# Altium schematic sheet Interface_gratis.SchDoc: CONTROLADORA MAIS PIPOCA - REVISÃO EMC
size A3; DocumentNumber: GA0050; SheetNumber: 17; SheetTotal: 17
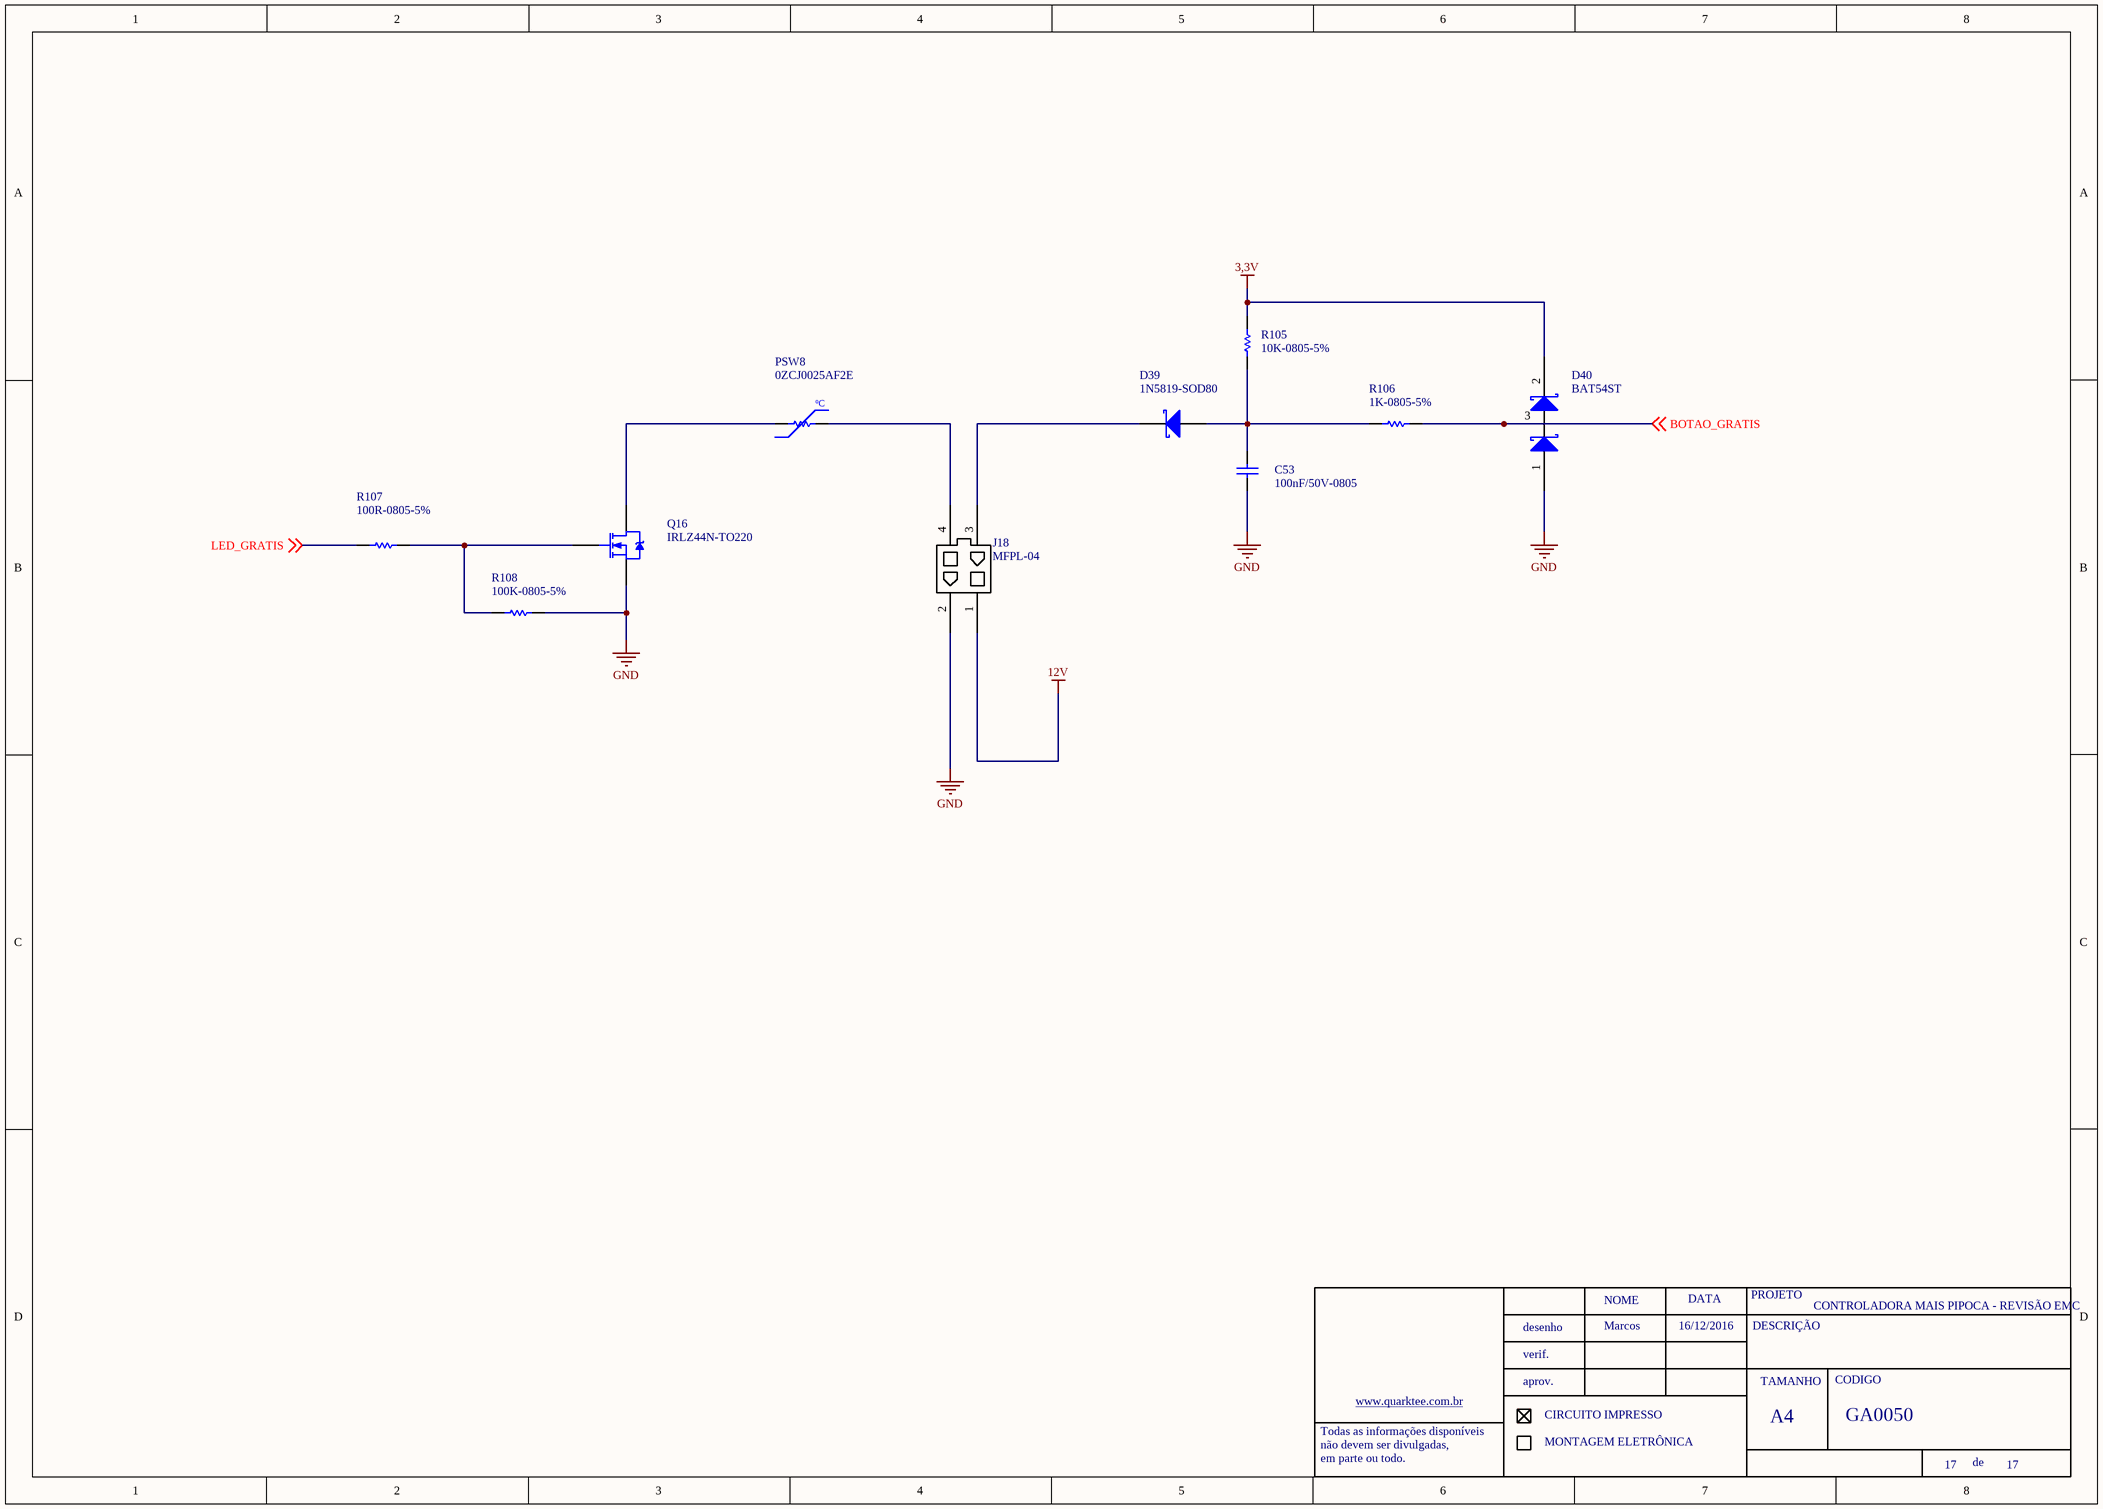
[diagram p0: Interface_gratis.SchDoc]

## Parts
C53  100nF/50V-0805  [0805-REVISADO ONDA]
D39  1N5819-SOD80  [MINIMLEF/SOD80 - REVISADO ONDA]
D40  BAT54ST  [SOT23 - REVISADO ONDA]
J18  MFPL-04
PSW8  0ZCJ0025AF2E  [1206-REVISADO ONDA]
Q16  IRLZ44N-TO220  [TO220-3 EM PÉ]
R105  10K-0805-5%  [0805-REVISADO ONDA]
R106  1K-0805-5%  [0805-REVISADO ONDA]
R107  100R-0805-5%  [0805-REVISADO ONDA]
R108  100K-0805-5%  [0805-REVISADO ONDA]

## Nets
3,3V: D40.2 R105.2
12V: J18.1
GND: C53.1 D40.1 J18.2 Q16.3(S) R108.2
BOTAO_GRATIS: D40.3 R106.2 ; off-sheet BOTAO_GRATIS
LED_GRATIS: R107.1 ; off-sheet LED_GRATIS
NetC53_2: C53.2 D39.1(A) R105.1 R106.1
NetD39_2: D39.2(K) J18.3
NetJ18_4: J18.4 PSW8.2
NetPSW8_1: PSW8.1 Q16.2(D)
NetQ16_1: Q16.1(G) R107.2 R108.1

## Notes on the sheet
- Marcos
- 16/12/2016

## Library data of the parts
C53 = 100nF/50-0805-NPO
PSW8 = PTC 2A-120V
